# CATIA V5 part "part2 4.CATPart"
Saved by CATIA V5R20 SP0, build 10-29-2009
Part number: UFO底座4
Bounding box of the stored display mesh (mm): x -45 to 45, y -45 to 44.964, z -60 to 0
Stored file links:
  C:\Users\16057\Documents\180511420 创意设计\part2 4.CATPart
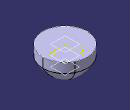
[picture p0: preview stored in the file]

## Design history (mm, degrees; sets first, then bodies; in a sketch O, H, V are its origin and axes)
Body1 (main body)
  Plane1: type Offset, RefPlane xy-plane, Offset 20, reversed
  Plane2: type Offset, RefPlane Plane1, Offset 20, reversed
  Sketch1 on Plane2, origin (0, 0, -40), H (1, 0, 0), V (0, 1, 0)
    circle A1 centre (0, 0) radius 30
    radius A1 = 30
  Sketch2 on Plane1, origin (0, 0, -20), H (1, 0, 0), V (0, 1, 0)
    circle A1 centre (0, 0) radius 45
    radius A1 = 45
  Sketch3 on xy-plane, origin (0, 0, 0), H (1, 0, 0), V (0, 1, 0)
    circle A1 centre (0, 0) radius 45
    radius A1 = 45
  Plane3: type Offset, RefPlane Plane2, Offset 20, reversed
  Sketch4 on Plane3, origin (0, 0, -60), H (1, 0, 0), V (0, 1, 0)
    circle A1 centre (0, 0) radius 0.05
    radius A1 = 0.05
  Loft1: solid, Sections (Sketch4; Sketch1; Sketch2)
  Pad1: profile face of Loft1, direction along Plane1, length 20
